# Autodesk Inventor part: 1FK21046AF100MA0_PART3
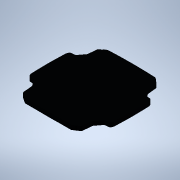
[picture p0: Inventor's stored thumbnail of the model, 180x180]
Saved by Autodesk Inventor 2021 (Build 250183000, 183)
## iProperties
Created: 2025-04
Part Number: 1FK21046AF100MA0_PART3
Material: Generic
Catalog Web Link: www.3dfindit.com
Description: -Servo synchronous motor
Document SubType Name: Modeling
Designer: psAdmin
Mass: 21.7019 g
Surface Area: 120.085 cm^2
Volume: 21.7019 cm^3
Density: 1 g/cm^3
Appearance: PSOLRGB-38-46-56
Category: PARTsolutions
Title: 1FK21046AF100MA0_PART3
Author: Cadenas PARTsolutions
Comments: Servo synchronous motor
Sending System: PARTsolutions
Preprocessor: ST-DEVELOPER v19.3
PSOL_IDENT_0: {$CADENAS_DATA/23d-libs/siemens_ag/_cat_/4f/2b/1fk21046af100ma0.prj},213 {VTYP=3D},{NB=1FK21046AF100
PSOL_IDENT_1: MA0_PART3},{LINA=1FK21046AF100MA0_PART3},{NN=1FK21046AF100MA0_PART3},{NOPRJ=TRUE},{DATE=19.08.2025 1
PSOL_IDENT_2: 4:00:37},{GEOMDATE=30.07.2025 02:01:06},{VERSION=},{LINEID=10},{WBVAR=},{WBNUMERIC=}  {NB=1FK21046AF
PSOL_IDENT_3: 100MA0_PART3},{LINA=1FK21046AF100MA0_PART3},{KT=DUMMY},{PREVIEW=../../../_pool_/cb/72/p_d211_xx_0043
PSOL_IDENT_4: 4j.png},{DESCSHORT=SIMOTICS S-1FK2 HD, SINAMICS S210 3AC 400V-480V, 3.2 Nm, 3000 rpm},{DESCLONG=SIMO
PSOL_IDENT_5: TICS S-1FK2 HD servo motor M0=3.2 Nm; PN = 1 kW at nN=3000 rpm (380-480 V); PN = 0.5 kW at nN=1500 r
PSOL_IDENT_6: pm (200-240 V); with holding brake; degree of protection IP64; cylindrical shaft D19x40mm; absolute
PSOL_IDENT_7: encoder 22-bit + 12-bit multiturn (encoder AM22DQC); with OCC interface; plug size M17, rotatable; S
PSOL_IDENT_8: IMOTICS S-1FK2 servomotorfor a wide range of uses in industrial environments. SIMOTICS S‑1FK2 servom
PSOL_IDENT_9: otors are compact synchronous motors with a high dynamic performance that set themselves apart as a
PSOL_IDENT_10: result of their high power density, degree of protection and overload capability. The motors are ava
PSOL_IDENT_11: ilable in two variants: as High Dynamic variant (highest dynamic performance as a result of the low
PSOL_IDENT_12: intrinsic moment of inertia for applications demanding a high dynamic performance with low moved mas
PSOL_IDENT_13: ses) - and as Compact variant (precise and stable closed-loop control for medium up to large moved m
PSOL_IDENT_14: asses as a result of a medium intrinsic moment of inertia). SIMOTICSS‑1FK2 servomotors fully exploit
PSOL_IDENT_15: their strengths in a system with the SINAMICSS210 frequency converter and simple connection using t
PSOL_IDENT_16: he one cable connection (OCC). Advantages include the short control and positioning times, fast and
PSOL_IDENT_17: precise correction of disturbing quantities as well as stable control with a high dynamic performanc
PSOL_IDENT_18: e. The servo motors can be configured to address a wide range of requirements. For example with and
PSOL_IDENT_19: without holding brake, IP64 or IP65 degree of protection, singleturn or multiturn absolute encoders
PSOL_IDENT_20: - to name just a few. Further, the servomotors are available in different shaft heights extending fr
PSOL_IDENT_21: om 20 to 100. A shaft sealing ring is available to achieve an IP65 degree of protection and for subs
PSOL_IDENT_22: equent mounting at the motor or as spare part. SIMOTICS - the optimum motor for each and every motio
PSOL_IDENT_23: n control application.},{INTNO=195125049673},{SUPPLIERALTNO=1FK2104-6AF10-0MA0},{MANUID=1FK21046AF10
PSOL_IDENT_24: 0MA0},{MANUNAME=Siemens},{MANUTYPEDESC=Synchronous motor 1FK2-HD 3.2 NM},{AAU732=SIMOTICS},{AAO057=S
PSOL_IDENT_25: -1FK2},{AAU734=SIMOTICS S-1FK2 HD servo motor M0=3.2 Nm; PN = 1 kW at nN=3000 rpm (380-480 V); PN =
PSOL_IDENT_26: 0.5 kW at nN=1500 rpm (200-240 V); with holding brake; degree of protection IP64; cylindrical shaft
PSOL_IDENT_27: D19x40mm; absolute encoder 22-bit + 12-bit multiturn (encoder AM22DQC); with OCC interface; plug siz
PSOL_IDENT_28: e M17, rotatable;},{AAW338=Synchronous motor 1FK2-HD 3.2 NM},{AAO742=SIMOTICS},{AAO663=4042948694534
PSOL_IDENT_29: },{NOCUPEROU=1},{PRICEQUANTITY=1},{QUANTITYMIN=1},{QUANTITYINT=1},{CTN=85015220},{COO=DE},{AAO676=1F
PSOL_IDENT_30: K2104-6AF10-0MA0},{AAO677=Siemens AG},{ORDERUNIT=C62},{CONTENTUNIT=C62}
NB: 1FK21046AF100MA0_PART3
NT: Servo synchronous motor
NBSYN: $MANUID._PART3
LINA: 1FK21046AF100MA0_PART3
CATALOG: SIEMENS
PREVIEW: ../../../_pool_/cb/72/p_d211_xx_00434j.png
DESCSHORT: SIMOTICS S-1FK2 HD, SINAMICS S210 3AC 400V-480V, 3.2 Nm, 3000 rpm
DESCLONG: SIMOTICS S-1FK2 HD servo motor M0=3.2 Nm; PN = 1 kW at nN=3000 rpm (380-480 V); PN = 0.5 kW at nN=1500 rpm (200-240 V); with holding brake; degree of protection
INTNO: 195125049673
SUPPLIERALTNO: 1FK2104-6AF10-0MA0
MANUID: 1FK21046AF100MA0
MANUNAME: Siemens
MANUTYPEDESC: Synchronous motor 1FK2-HD 3.2 NM
AAU732: SIMOTICS
AAO057: S-1FK2
AAU734: SIMOTICS S-1FK2 HD servo motor M0=3.2 Nm; PN = 1 kW at nN=3000 rpm (380-480 V); PN = 0.5 kW at nN=1500 rpm (200-240 V); with holding brake; degree of protection
AAW338: Synchronous motor 1FK2-HD 3.2 NM
AAO742: SIMOTICS
AAO663: 4042948694534.0
NOCUPEROU: 1
PRICEQUANTITY: 1
QUANTITYMIN: 1
QUANTITYINT: 1
CTN: 85015220
COO: DE
ARTICLENO: 1FK21046AF100MA0_PART3
BOMINFO: 1FK21046AF100MA0_PART3
CREATOR: CADENAS GmbH
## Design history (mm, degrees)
feature "2025_04_17_14_59_39_0083"
body "Solid1"
